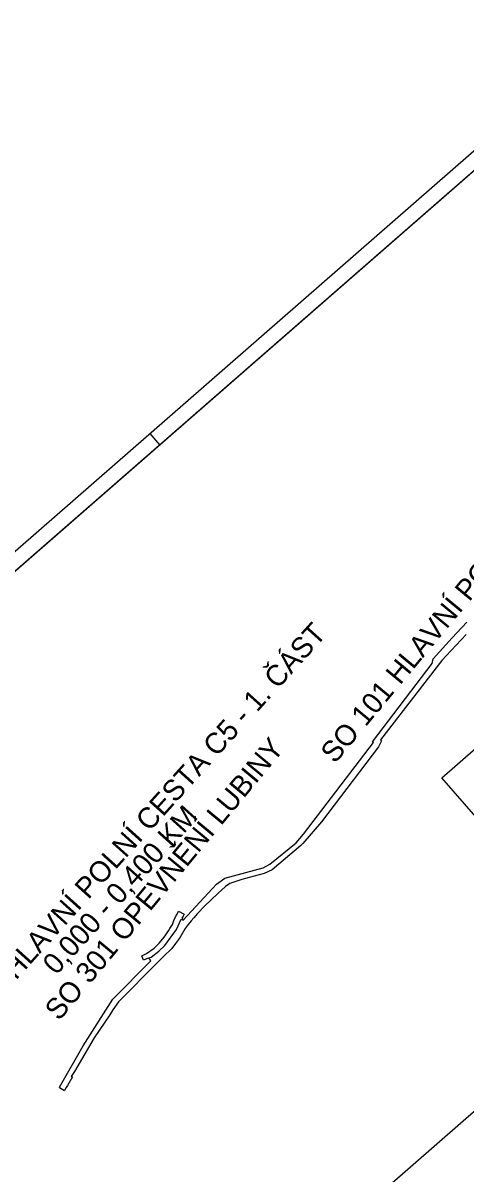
# Model space of a CAD drawing. Extents: x -482105 to -477964, y -1113879 to -1109998.
# Drawn here: x -479945 to -479200, y -1111934 to -1109998 of the extents above; entities that cross this region are included whole.
import ezdxf

# ---------------------------------------------------------------- set-up
doc = ezdxf.new("R2010")
doc.units = 0
for name, color, linetype in [('hranice staveniště', 7, 'Continuous'), ('Implicitní', 7, 'Continuous'), ('legenda', 7, 'Continuous'), ('rozpiska', 7, 'Continuous'), ('SO', 7, 'Continuous')]:
    doc.layers.add(name, color=color, linetype=linetype)

msp = doc.modelspace()

# ---------------------------------------------------------------- linework, layer by layer
at = {"layer": 'hranice staveniště'}
for p, q in [((-479222.9, -1111032.4), (-479198.3, -1111005.9)), ((-479199.9, -1111026.5), (-479233.4, -1111062.6)), ((-479255.4, -1111067.8), (-479222.9, -1111032.4)), ((-479539.3, -1111428.7), (-479564.3, -1111435.3)), ((-479604.1, -1111450.3), (-479617.2, -1111462.5)), ((-479564.3, -1111435.3), (-479577, -1111438.9)), ((-479617.2, -1111462.5), (-479639.9, -1111483.8)), ((-479639.9, -1111483.8), (-479651.2, -1111495.8)), ((-479678.7, -1111505.6), (-479675.3, -1111507.3)), ((-479662.2, -1111508.4), (-479667.3, -1111514.3)), ((-479657.8, -1111503.4), (-479662.2, -1111508.4)), ((-479651.2, -1111495.8), (-479657.8, -1111503.4)), ((-479672.2, -1111521.1), (-479680.7, -1111535.7)), ((-479667.3, -1111514.3), (-479672.2, -1111521.1)), ((-479688.6, -1111546.6), (-479694.8, -1111555)), ((-479683.5, -1111539.6), (-479688.6, -1111546.6)), ((-479680.7, -1111535.7), (-479683.5, -1111539.6)), ((-479708.4, -1111568), (-479718.9, -1111578.6)), ((-479694.8, -1111555), (-479708.4, -1111568)), ((-479731.2, -1111574.1), (-479733.8, -1111571.3)), ((-479793.7, -1111657.9), (-479799, -1111666.5)), ((-479799, -1111666.5), (-479825.1, -1111705.1)), ((-479861.4, -1111770.8), (-479869.9, -1111785.4)), ((-479883.5, -1111788.6), (-479874.9, -1111793.5))]:
    msp.add_line(p, q, dxfattribs=at)
for points in [[(-479233.4, -1111062.6), (-479240.5, -1111070.3), (-479343.5, -1111204.1), (-479341.9, -1111205.5), (-479347.1, -1111215.5), (-479443.2, -1111342)], [(-479473.3, -1111362.8), (-479355.4, -1111208.6), (-479357.1, -1111207.2), (-479256.8, -1111075.3), (-479255.4, -1111067.8)], [(-479443.2, -1111342), (-479474.1, -1111378.4), (-479477.6, -1111381.6)], [(-479675.3, -1111507.3), (-479619.5, -1111446.4), (-479605.5, -1111436.6), (-479541.3, -1111418.9), (-479529.9, -1111412.9), (-479485.5, -1111376.9), (-479473.3, -1111362.8)], [(-479477.6, -1111381.6), (-479525.9, -1111422.6), (-479539.3, -1111428.7)], [(-479577, -1111438.9), (-479597, -1111445.5), (-479604.1, -1111450.3)], [(-479733.8, -1111571.3), (-479729.6, -1111569.6), (-479716.3, -1111559.5), (-479706.3, -1111549.7), (-479686.8, -1111522.9), (-479678.7, -1111505.6)], [(-479883.5, -1111788.6), (-479883.3, -1111788.1), (-479843.9, -1111718.6), (-479793.8, -1111639.9), (-479730.2, -1111575.3), (-479731.2, -1111574.1)], [(-479718.9, -1111578.6), (-479784.3, -1111644.4), (-479793.7, -1111657.9)], [(-479825.1, -1111705.1), (-479858.4, -1111761.7), (-479863.7, -1111769.8), (-479861.4, -1111770.8)], [(-479870, -1111785.4), (-479872.1, -1111788.7), (-479874.9, -1111793.5)]]:
    msp.add_lwpolyline(points, dxfattribs=at)
at = {"layer": 'Implicitní'}
msp.add_lwpolyline([(-479733.2, -1111571.9), (-479733.9, -1111572.2), (-479734.3, -1111571.1), (-479742, -1111574.3), (-479745, -1111567.1), (-479737, -1111563.4), (-479724.5, -1111554.2), (-479715.7, -1111545.7), (-479709.7, -1111538.8), (-479706.1, -1111533.6), (-479702.6, -1111528.5), (-479700.4, -1111525), (-479698.1, -1111521.4), (-479695.8, -1111517.8), (-479693.5, -1111514.3), (-479691, -1111508), (-479688.4, -1111501.7), (-479685.9, -1111497), (-479683.3, -1111492.3), (-479673.8, -1111496.8), (-479675.8, -1111500.4), (-479677.7, -1111504), (-479676.7, -1111504.6), (-479677.5, -1111506.2)], dxfattribs=at)
at = {"layer": 'legenda'}
msp.add_lwpolyline([(-481125.9, -1113843.4), (-479562.4, -1112479.2), (-479722.1, -1112296.2), (-478939.3, -1111613.2), (-479240.6, -1111267.9), (-478575.9, -1110687.9), (-479060.3, -1110136.7), (-481297.1, -1112088.2), (-481198.7, -1112201), (-481971, -1112874.8)], close=True, dxfattribs=at)
at = {"layer": 'rozpiska'}
msp.add_line((-479714.7, -1110707.6), (-479731.1, -1110688.8), dxfattribs=at)
for points in [[(-477963.6, -1111117.5), (-481128.3, -1113878.7), (-482104.7, -1112759.7), (-478939.9, -1109998.4)], [(-477998.9, -1111115.1), (-481125.9, -1113843.4), (-482069.4, -1112762.1), (-478942.3, -1110033.7)]]:
    msp.add_lwpolyline(points, close=True, dxfattribs=at)

# ---------------------------------------------------------------- texts
at = {"layer": 'SO'}
for s, rotation, p in [('SO 101 HLAVNÍ POLNÍ CESTA C5 - 2. ČÁST', 50.3503, (-479420.3, -1111245.2)), ('SO 101 HLAVNÍ POLNÍ CESTA C5 - 1. ČÁST', 48.0095, (-480071.7, -1111736.6)), ('SO 301 OPEVNĚNÍ LUBINY', 50.3503, (-479884.2, -1111677.9)), ('0,000 - 0,400 KM', 48.0095, (-479888.9, -1111600.9))]:
    msp.add_text(s, height=35, rotation=rotation, dxfattribs=at).set_placement(p)

doc.saveas('drawing.dxf')
